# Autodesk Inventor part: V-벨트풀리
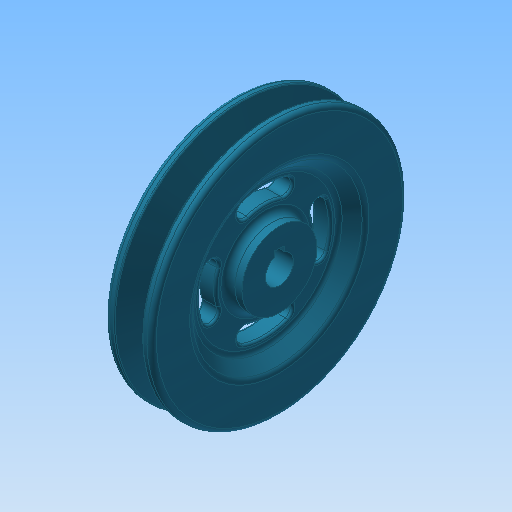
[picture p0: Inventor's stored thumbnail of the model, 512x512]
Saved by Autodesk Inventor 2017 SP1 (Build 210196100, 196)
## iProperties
Created: 2015-12
Part Number: V-벨트풀리
Document SubType Name: Modeling
Designer: mdu
Density: 8.08 g/cm^3
Material: 스테인리스강
Mass: 919.298 g
Surface Area: 326.109 cm^2
Volume: 113.774 cm^3
Appearance: 터키옥색
Author: mdu
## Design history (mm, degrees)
sketch "스케치1"
  geometry: L1 (-10, 0)-(10, 0); L2 (-10, 0)-(-10, 16); L3 (-10, 16)-(-4, 16); L4 (-4, 16)-(-4, 31); L5 (-4, 31)-(-10, 37); L6 (-10, 37)-(-10, 54.5); L7 (-10, 54.5)-(-5.976, 54.5); L8 (-5.976, 54.5)-(-2.154, 42); L9 (-2.154, 42)-(2.154, 42); L10 (2.154, 42)-(5.976, 54.5); L11 (5.976, 54.5)-(10, 54.5); L12 (10, 54.5)-(10, 37); L13 (10, 37)-(4, 31); L14 (4, 31)-(4, 16); L15 (4, 16)-(10, 16); L16 (10, 16)-(10, 0); L17 (-4.6, 50)-(4.6, 50); 2 further points
  constraints: 34 end point, 7 parallel, 6 equal length, 5 collinear, 3 perpendicular, 2 point on line, 1 coincident, 1 horizontal, 1 midpoint
  dimensions: "d0" = 20 distance of L1.start L1.end; "d1" = 9.2 distance of L17.start L17.end; "d2" = 34 deg angle of L10 L8; "d3" = 4.5 distance between parallel lines of L7 L17; "d4" = 8 distance between parallel lines of L9 L17; "d6" = 100 diameter of L17 L1; "d7" = 32 diameter of L3 L1; "d8" = 74 diameter of L5.end L1; "d9" = 6 distance of L2.end L3.end; "d10" = 135 deg angle of L4 L5
revolve "회전1" sketch "스케치1" stored, may be unused: angle "d11" = 90 deg
fillet "모깎기1" dims "d12" = 2, "d13" = 0.5, "d14" = 1, "d15" = 3
sketch "스케치2"
  geometry: L1 (-2, 5.657)-(-2, 7.8); L2 (-2, 7.8)-(2, 7.8); L3 (2, 7.8)-(2, 5.657); A1 r 6 centre (0, 0) between (-2, 5.657) and (2, 5.657); 1 further point
  constraints: 6 end point, 2 parallel, 2 point on circle, 1 centre point, 1 coincident, 1 perpendicular, 1 vertical
  dimensions: "d16" = 12 diameter of A1; "d17" = 4 distance of L1.end L2.end; "d18" = 13.8 dimension on A1 L2 (computed from d16)
extrude "돌출1" cut sketch "스케치2" stored distance "d19" = 10; taper "d20" = 0 deg
sketch "스케치3"
  geometry: L1 (0, 0)-(0, 24.5); L2 (0, 0)-(-8.379, 23.022); C1 r 29.757 at (0, 0) reference; C2 r 19 at (0, 0) reference; A1 r 24.5 centre (0, 0) between (0, 24.5) and (-8.379, 23.022); A2 r 3.3 centre (-8.379, 23.022) between (-9.508, 26.123) and (-7.251, 19.921); A3 r 3.3 centre (8.379, 23.022) between (7.251, 19.921) and (9.508, 26.123); A4 r 27.8 centre (0, 0) between (9.508, 26.123) and (-9.508, 26.123); A5 r 21.2 centre (0, 0) between (7.251, 19.921) and (-7.251, 19.921); 1 further point
  constraints: 10 point on circle, 5 centre point, 4 coincident, 4 end point, 1 point on line, 1 symmetric about line, 1 tangent, 1 vertical, 1 other
  dimensions: "d24" = 49 diameter of A1; "d27" = 20 deg angle of L1 L2; "d29" = 6.6 diameter of A2
extrude "돌출2" cut sketch "스케치3" stored distance "d30" = 10; taper "d31" = 0 deg
fillet "모깎기2" dims "d32" = 1
node "솔리드1"
pattern_circular "원형 패턴1" dims angle "d34" = 360 deg
